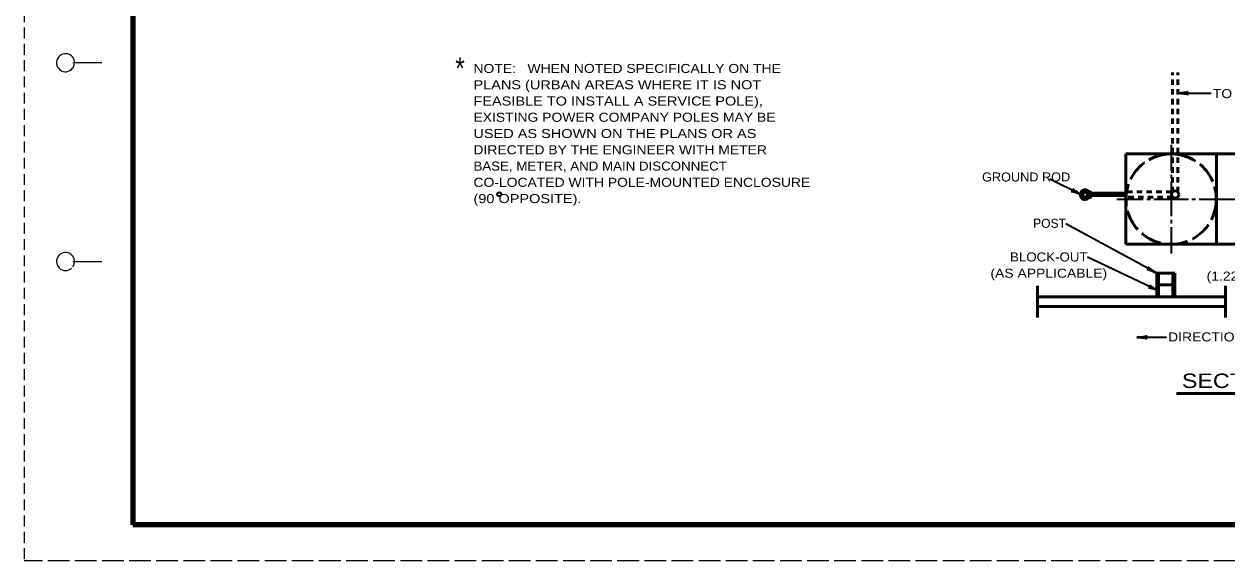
# Model space of a CAD drawing. Extents: x -68 to 612, y -58 to 382.
# Drawn here: x -67.7 to 265, y -57.9 to 90.7 of the extents above; entities that cross this region are included whole.
import ezdxf
from ezdxf.enums import TextEntityAlignment as Align

# ---------------------------------------------------------------- set-up
doc = ezdxf.new("R2010")
doc.units = 0
for name, pattern in [('LONG_DASHED', [7.5, 6, -1.5]), ('MEDIUM_DASHED', [4.5, 3, -1.5]), ('SHORT_DASHED', [2.7, 1.5, -1.2])]:
    doc.linetypes.add(name, pattern=pattern)
doc.layers.add('1', color=7, linetype='Continuous', lineweight=53)
doc.layers.add('61', color=7, linetype='Continuous', lineweight=35)

msp = doc.modelspace()

# ---------------------------------------------------------------- linework, layer by layer
at = {"layer": '1', "linetype": 'MEDIUM_DASHED', "lineweight": 13}
msp.add_line((-67.611, 382.166), (-67.671, -57.874), dxfattribs=at)
at = {"layer": '1', "linetype": 'SHORT_DASHED'}
for p, q in [((249.897, 44.136), (249.897, 77.23)), ((251.397, 44.136), (251.397, 77.23)), ((249.647, 44.225), (237.054, 44.225)), ((249.985, 42.725), (237.054, 42.725))]:
    msp.add_line(p, q, dxfattribs=at)
at = {"layer": '1', "lineweight": 35}
for p, q in [((251.397, 71.55), (260.573, 71.55)), ((249.554, 57.23), (249.554, 54.73)), ((249.554, 54.73), (249.554, 49.98)), ((224.714, 43.44), (216.007, 47.781)), ((249.554, 48.98), (249.554, 47.98)), ((249.554, 46.98), (249.554, 42.23)), ((234.554, 42.23), (237.054, 42.23)), ((237.054, 42.23), (241.804, 42.23)), ((242.804, 42.23), (243.804, 42.23)), ((249.554, 42.23), (254.304, 42.23)), ((255.304, 42.23), (256.304, 42.23)), ((257.304, 42.23), (262.054, 42.23)), ((262.054, 42.23), (270.054, 42.23)), ((245.554, 21.729), (220.415, 35.351)), ((249.554, 36.48), (249.554, 35.48)), ((249.554, 34.48), (249.554, 29.729)), ((249.554, 29.729), (249.554, 27.229)), ((246.054, 16.842), (226.435, 26.204)), ((248.277, 3.983), (240.048, 3.983))]:
    msp.add_line(p, q, dxfattribs=at)
at = {"layer": '1'}
for p, q in [((237.054, 54.73), (270.054, 54.73)), ((237.054, 54.73), (237.054, 29.729)), ((262.054, 54.73), (262.054, 29.729)), ((237.054, 29.729), (270.054, 29.729)), ((246.054, 15.229), (246.054, 21.729)), ((250.054, 15.229), (250.054, 21.729)), ((250.554, 15.229), (250.554, 21.729)), ((212.554, 18.229), (212.554, 9.479)), ((246.054, 18.479), (250.054, 18.479)), ((264.554, 18.229), (264.554, 9.479)), ((212.554, 15.229), (264.554, 15.229)), ((212.554, 12.479), (264.554, 12.479)), ((251.024, -11.547), (299.314, -11.547))]:
    msp.add_line(p, q, dxfattribs=at)
at = {"layer": '1', "lineweight": 90}
msp.add_line((237.054, 43.475), (227.054, 43.475), dxfattribs=at)
msp.add_lwpolyline([(226.554, 43.975), (227.054, 43.975), (227.054, 42.975), (226.554, 42.975), (226.589, 42.975)], dxfattribs=at)
at = {"layer": '1', "lineweight": 35}
msp.add_lwpolyline([(244.804, 42.23), (249.554, 42.23), (249.554, 37.48)], dxfattribs=at)
at = {"layer": '1'}
msp.add_lwpolyline([(245.554, 15.229), (245.554, 21.729), (250.554, 21.729)], dxfattribs=at)
at = {"layer": '1', "linetype": 'LONG_DASHED'}
msp.add_circle((249.554, 42.23), 12.5, dxfattribs=at)
at = {"layer": '1', "lineweight": 35}
msp.add_circle((63.738, 43.559), 0.559, dxfattribs=at)
at = {"layer": '1'}
msp.add_circle((250.647, 43.475), 1, dxfattribs=at)
at = {"layer": '1', "lineweight": 90}
msp.add_arc((225.713, 43.459), 1, 31.09219, 331.0803, dxfattribs=at)
at = {"layer": '1', "lineweight": 40}
for centre, major_axis, ratio, start_param, end_param in [((252.517, 71.338), (-1.756, 0.176), 0.07063, 3.1407148, 5.41811), ((252.517, 71.338), (-1.756, 0.176), 0.07063, 3.1407148, 5.41811), ((252.488, 71.826), (-1.786, -0.156), 0.122415, 0.8963533, 3.1415927), ((252.488, 71.826), (-1.786, -0.156), 0.122415, 0.8963533, 3.1415927), ((223.614, 43.679), (1.668, -0.657), 0.122415, 0.8963533, 3.1415927), ((223.614, 43.679), (1.668, -0.657), 0.122415, 0.8963533, 3.1415927), ((223.805, 44.129), (-1.494, 0.941), 0.07063, 6.2823074, 8.5597026), ((223.805, 44.129), (-1.494, 0.941), 0.07063, 6.2823074, 8.5597026), ((244.67, 22.449), (-1.461, 0.991), 0.07063, 6.2823074, 8.5597026), ((244.67, 22.449), (-1.461, 0.991), 0.07063, 6.2823074, 8.5597026), ((244.463, 22.006), (1.644, -0.713), 0.122415, 0.8963533, 3.1415927), ((244.463, 22.006), (1.644, -0.713), 0.122415, 0.8963533, 3.1415927), ((244.95, 17.063), (1.679, -0.628), 0.122415, 0.8963533, 3.1415927), ((245.134, 17.516), (1.51, -0.915), 0.07063, 3.1407148, 5.41811), ((241.168, 3.771), (-1.756, 0.176), 0.07063, 3.1407148, 5.41811), ((241.168, 3.771), (-1.756, 0.176), 0.07063, 3.1407148, 5.41811), ((241.139, 4.259), (-1.786, -0.156), 0.122415, 0.8963533, 3.1415927), ((241.139, 4.259), (-1.786, -0.156), 0.122415, 0.8963533, 3.1415927)]:
    msp.add_ellipse(centre, major_axis=major_axis, ratio=ratio, start_param=start_param, end_param=end_param, dxfattribs=at)
at = {"layer": '61', "lineweight": 13}
for p, q in [((-54.191, 79.986), (-46.191, 79.986)), ((-54.171, 24.966), (-46.191, 24.966))]:
    msp.add_line(p, q, dxfattribs=at)
at = {"layer": '61', "lineweight": 158}
msp.add_line((601.449, -47.874), (-37.611, -47.854), dxfattribs=at)
at = {"layer": '61', "linetype": 'LONG_DASHED', "lineweight": 13}
msp.add_line((612.389, -57.854), (-67.671, -57.874), dxfattribs=at)
at = {"layer": '61', "lineweight": 158}
msp.add_lwpolyline([(601.429, 372.166), (-37.611, 372.166), (-37.611, -47.854)], dxfattribs=at)
at = {"layer": '61', "lineweight": 13}
for centre, start, end in [((-56.194, 79.967), 322.67175, 321.71615), ((-56.194, 24.967), 323.13009, 312.31439)]:
    msp.add_arc(centre, 2.5, start, end, dxfattribs=at)

# ---------------------------------------------------------------- texts
at = {"layer": '1'}
for s, height, width, p in [('*', 6, 0.85, (51.567, 75.442)), ('NOTE:   WHEN NOTED SPECIFICALLY ON THE', 2.5, 1.15, (56.607, 77.124)), ('PLANS (URBAN AREAS WHERE IT IS NOT', 2.5, 1.2, (56.607, 72.624)), ('FEASIBLE TO INSTALL A SERVICE POLE),', 2.5, 1.2, (56.607, 68.124)), ('EXISTING POWER COMPANY POLES MAY BE', 2.5, 1.15, (56.607, 63.624)), ('USED AS SHOWN ON THE PLANS OR AS', 2.5, 1.2, (56.607, 59.124)), ('DIRECTED BY THE ENGINEER WITH METER', 2.5, 1.15, (56.607, 54.624)), ('BASE, METER, AND MAIN DISCONNECT', 2.5, 1.1, (56.607, 50.124)), ('CO-LOCATED WITH POLE-MOUNTED ENCLOSURE', 2.5, 1.15, (56.607, 45.624)), ('(90 OPPOSITE).', 2.5, 1.2, (56.607, 41.124))]:
    msp.add_text(s, height=height, dxfattribs=dict(at, width=width)).set_placement(p)
for s, height, width, p in [('TO JUNCTION BOX', 2.5, 1.15, (278.601, 70.17)), ('GROUND ROD', 2.5, 1.05, (209.441, 47.109)), ('BLOCK-OUT', 2.5, 1.1, (215.71, 24.975)), ('(AS APPLICABLE)', 2.5, 1.15, (215.71, 20.475)), ('(1.22m MIN.)', 2.5, 1.15, (270.569, 19.679)), ('DIRECTION OF TRAFFIC', 2.5, 1.15, (271.145, 2.852)), ('SECTION "B-B"', 4, 1.2, (275.325, -10.027))]:
    msp.add_text(s, height=height, dxfattribs=dict(at, width=width)).set_placement(p, align=Align.CENTER)
msp.add_text('POST', height=2.5, dxfattribs=at).set_placement((215.919, 34.29), align=Align.CENTER)

doc.saveas('drawing.dxf')
